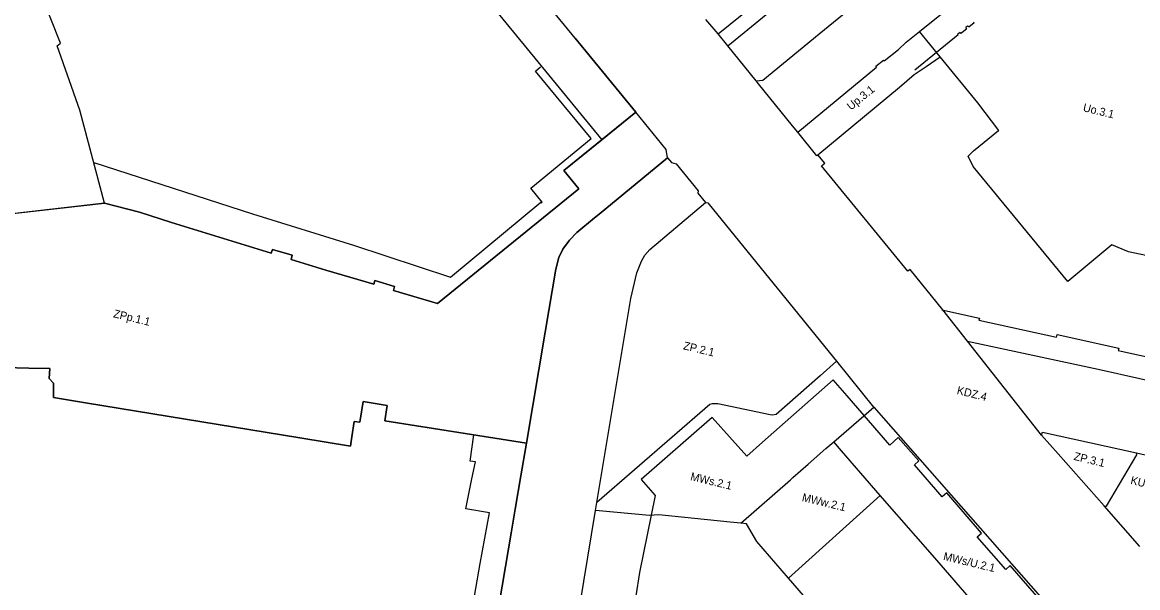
# Model space of a CAD drawing. Extents: x 7429686 to 7432896, y 5547954 to 5550600.
# Drawn here: x 7430296 to 7430853, y 5549179 to 5549462 of the extents above; entities that cross this region are included whole.
import ezdxf

# ---------------------------------------------------------------- set-up
doc = ezdxf.new("R2010")
doc.units = 0
for name, color, linetype in [('linie rozgraniczające', 7, 'Continuous'), ('nieprzekraczalna linia zabudowy', 7, 'Continuous'), ('obowiązująca linia zabudowy', 7, 'Continuous'), ('oznaczenia przeznaczeń', 7, 'Continuous')]:
    doc.layers.add(name, color=color, linetype=linetype)

msp = doc.modelspace()

# ---------------------------------------------------------------- linework, layer by layer
at = {"layer": 'linie rozgraniczające'}
for p, q in [((7430572.38, 5549453.75), (7430602.76, 5549416.71)), ((7430602.76, 5549416.71), (7430566.84, 5549387.58)), ((7430617.97, 5549398.17), (7430602.76, 5549416.71)), ((7430618.59, 5549393.98), (7430617.97, 5549398.17)), ((7430584.47, 5549365.84), (7430618.59, 5549393.98)), ((7430566.84, 5549387.58), (7430574.26, 5549378.42)), ((7430574.26, 5549378.42), (7430503.7, 5549321.19)), ((7430337.34, 5549371.27), (7430272.16, 5549363.93)), ((7430354.77, 5549366.88), (7430337.34, 5549371.27)), ((7430370.74, 5549361.7), (7430354.77, 5549366.88)), ((7430420.6, 5549346.33), (7430370.74, 5549361.7)), ((7430421.24, 5549348.13), (7430420.6, 5549346.33)), ((7430431.09, 5549345.3), (7430421.24, 5549348.13)), ((7430564.26, 5549344.2), (7430566.35, 5549348.4)), ((7430430.65, 5549343.27), (7430431.09, 5549345.3)), ((7430447.94, 5549337.81), (7430430.65, 5549343.27)), ((7430562.78, 5549338.29), (7430564.26, 5549344.2)), ((7430471.79, 5549330.8), (7430447.94, 5549337.81)), ((7430557.54, 5549307), (7430562.78, 5549338.29)), ((7430472.33, 5549332.69), (7430471.79, 5549330.8)), ((7430482.21, 5549329.77), (7430472.33, 5549332.69)), ((7430481.77, 5549327.66), (7430482.21, 5549329.77)), ((7430503.7, 5549321.19), (7430481.77, 5549327.66)), ((7430548.12, 5549251.59), (7430557.54, 5549307)), ((7430299.57, 5549289), (7430310.07, 5549288.78)), ((7430310.07, 5549288.78), (7430299.57, 5549289)), ((7430310.07, 5549288.78), (7430309.7, 5549283.85)), ((7430309.7, 5549283.85), (7430310.07, 5549288.78)), ((7430309.7, 5549283.85), (7430311.83, 5549281.48)), ((7430311.83, 5549281.48), (7430309.7, 5549283.85)), ((7430460.96, 5549254.64), (7430462.06, 5549262.36)), ((7430462.06, 5549262.36), (7430460.96, 5549254.64)), ((7430477.31, 5549262.67), (7430548.12, 5549251.59)), ((7430548.12, 5549251.59), (7430477.31, 5549262.67))]:
    msp.add_line(p, q, dxfattribs=at)
for points in [[(7430694.34, 5549455.8), (7430768.57, 5549516.43)], [(7430500.44, 5549507), (7430585.7, 5549402.87)], [(7430648.77, 5549449.84), (7430699.66, 5549491.66)], [(7430572.38, 5549453.75), (7430546.44, 5549485.44)], [(7430315.31, 5549451.27), (7430305.6, 5549475.67)], [(7430744.44, 5549457), (7430755.42, 5549465.8)], [(7430643.85, 5549455.8), (7430637.8, 5549463.05)], [(7430602.76, 5549416.71), (7430572.38, 5549453.75)], [(7430648.77, 5549449.84), (7430643.85, 5549455.8)], [(7430666.17, 5549432.65), (7430694.34, 5549455.8)], [(7430737.8, 5549451.68), (7430744.44, 5549457)], [(7430754.83, 5549444.29), (7430744.44, 5549457)], [(7430313.63, 5549449.85), (7430315.31, 5549451.27)], [(7430324.98, 5549417.82), (7430313.63, 5549449.85)], [(7430662.88, 5549432.41), (7430648.77, 5549449.84)], [(7430726.87, 5549442.35), (7430734.04, 5549448)], [(7430734.04, 5549448), (7430737.8, 5549451.68)], [(7430722.71, 5549439.66), (7430726.46, 5549442.73)], [(7430726.46, 5549442.73), (7430726.87, 5549442.35)], [(7430747.87, 5549439.58), (7430754.83, 5549444.29)], [(7430773.6, 5549421.33), (7430754.83, 5549444.29)], [(7430683.69, 5549406.71), (7430722.96, 5549439.25)], [(7430722.96, 5549439.25), (7430722.71, 5549439.66)], [(7430741.81, 5549435.48), (7430747.87, 5549439.58)], [(7430662.88, 5549432.41), (7430666.17, 5549432.65)], [(7430664.07, 5549430.93), (7430662.88, 5549432.41)], [(7430681.11, 5549409.99), (7430664.07, 5549430.93)], [(7430734.41, 5549429.24), (7430741.81, 5549435.48)], [(7430693.66, 5549395.47), (7430734.41, 5549429.24)], [(7430784.03, 5549407.63), (7430773.6, 5549421.33)], [(7430337.34, 5549371.27), (7430324.98, 5549417.82)], [(7430585.7, 5549402.87), (7430602.76, 5549416.71)], [(7430683.69, 5549406.71), (7430681.11, 5549409.99)], [(7430337.34, 5549371.27), (7430354.77, 5549366.88), (7430370.74, 5549361.7), (7430420.6, 5549346.33), (7430421.24, 5549348.13), (7430431.09, 5549345.3), (7430430.65, 5549343.27), (7430447.94, 5549337.81), (7430471.79, 5549330.8), (7430472.33, 5549332.69), (7430482.21, 5549329.77), (7430481.77, 5549327.66), (7430503.7, 5549321.19), (7430574.26, 5549378.42), (7430566.84, 5549387.58), (7430585.7, 5549402.87)], [(7430693.14, 5549395.03), (7430683.69, 5549406.71)], [(7430771.5, 5549397.49), (7430783.91, 5549407.54)], [(7430783.91, 5549407.54), (7430784.03, 5549407.63)], [(7430768.87, 5549394.83), (7430771.5, 5549397.49)], [(7430618.59, 5549393.98), (7430584.47, 5549365.84), (7430582.03, 5549363.94), (7430573.22, 5549356.61), (7430569.64, 5549352.91), (7430566.35, 5549348.4), (7430564.26, 5549344.2), (7430562.78, 5549338.29), (7430557.54, 5549307), (7430548.12, 5549251.59), (7430545.34, 5549235.21), (7430542.51, 5549218.56), (7430540.65, 5549207.55), (7430533.01, 5549162.52), (7430527.32, 5549127.87), (7430525.7, 5549118.01), (7430522.95, 5549101.23), (7430520.88, 5549089.31), (7430518.75, 5549077.07)], [(7430618.59, 5549393.98), (7430620.66, 5549391.55)], [(7430620.66, 5549391.55), (7430622.95, 5549390.88)], [(7430693.66, 5549395.47), (7430693.14, 5549395.03)], [(7430697.19, 5549391.24), (7430693.66, 5549395.47)], [(7430695.58, 5549389.89), (7430697.19, 5549391.24)], [(7430771.22, 5549389.57), (7430768.87, 5549394.83)], [(7430622.95, 5549390.88), (7430633.84, 5549377.42)], [(7430738.69, 5549337.39), (7430695.58, 5549389.89)], [(7430818.63, 5549332.25), (7430771.22, 5549389.57)], [(7430633.84, 5549377.42), (7430633.81, 5549376.39)], [(7430633.81, 5549376.39), (7430637.56, 5549371.57)], [(7430243.28, 5549369.29), (7430272.16, 5549363.93), (7430337.34, 5549371.27)], [(7430609.71, 5549348.2), (7430637.56, 5549371.57)], [(7430637.56, 5549371.57), (7430638.8, 5549371.41)], [(7430638.8, 5549371.41), (7430643.75, 5549365.32)], [(7430566.35, 5549348.4), (7430569.64, 5549352.91), (7430573.22, 5549356.61), (7430582.03, 5549363.94), (7430584.47, 5549365.84)], [(7430643.75, 5549365.32), (7430703.02, 5549292.37)], [(7430607.29, 5549345.32), (7430609.71, 5549348.2)], [(7430840.53, 5549350.59), (7430818.63, 5549332.25)], [(7430848.84, 5549346.95), (7430840.53, 5549350.59)], [(7430882.06, 5549340.05), (7430848.84, 5549346.95)], [(7430603.19, 5549336.62), (7430605.58, 5549342.31)], [(7430605.58, 5549342.31), (7430607.29, 5549345.32)], [(7430600.3, 5549323.68), (7430603.19, 5549336.62)], [(7430739.78, 5549338.18), (7430738.69, 5549337.39)], [(7430756.09, 5549318.13), (7430739.78, 5549338.18)], [(7430585.73, 5549236.85), (7430600.3, 5549323.68)], [(7430768.46, 5549302.43), (7430756.09, 5549318.13)], [(7430805.47, 5549255.48), (7430768.46, 5549302.43)], [(7430768.46, 5549302.43), (7430833.66, 5549288.37)], [(7430703.02, 5549292.37), (7430694.84, 5549285.16)], [(7430703.02, 5549292.37), (7430721.55, 5549269.55)], [(7430267.43, 5549289.84), (7430287.43, 5549289.21), (7430299.57, 5549289)], [(7430299.57, 5549289), (7430287.43, 5549289.21), (7430267.43, 5549289.84)], [(7430694.84, 5549285.16), (7430672.79, 5549265.74)], [(7430833.66, 5549288.37), (7430896.14, 5549274.49)], [(7430311.83, 5549281.48), (7430311.88, 5549274.24), (7430327.8, 5549271.63), (7430434.82, 5549254.16)], [(7430434.82, 5549254.16), (7430327.8, 5549271.63), (7430311.88, 5549274.24), (7430311.83, 5549281.48)], [(7430462.06, 5549262.36), (7430464.85, 5549262), (7430466.57, 5549272.33), (7430478.51, 5549270.29), (7430477.31, 5549262.67)], [(7430477.31, 5549262.67), (7430478.51, 5549270.29), (7430466.57, 5549272.33), (7430464.85, 5549262), (7430462.06, 5549262.36)], [(7430639.76, 5549270.8), (7430583.23, 5549221.89)], [(7430640.82, 5549271.09), (7430639.76, 5549270.8)], [(7430643.71, 5549271.17), (7430640.82, 5549271.09)], [(7430669.95, 5549265.61), (7430643.71, 5549271.17)], [(7430701.6, 5549252.19), (7430721.61, 5549269.49)], [(7430721.55, 5549269.55), (7430721.61, 5549269.49)], [(7430721.61, 5549269.49), (7430744.67, 5549243.3)], [(7430671.02, 5549265.52), (7430669.95, 5549265.61)], [(7430672.79, 5549265.74), (7430671.02, 5549265.52)], [(7430434.82, 5549254.16), (7430460.21, 5549250.09), (7430460.96, 5549254.64)], [(7430460.96, 5549254.64), (7430460.21, 5549250.09), (7430434.82, 5549254.16)], [(7430697.66, 5549248.78), (7430701.6, 5549252.19)], [(7430705.58, 5549247.62), (7430701.6, 5549252.19)], [(7430805.47, 5549255.48), (7430805.92, 5549257.02)], [(7430813.77, 5549246.1), (7430805.47, 5549255.48)], [(7430805.92, 5549257.02), (7430852.85, 5549246.65)], [(7430542.51, 5549218.56), (7430545.34, 5549235.21), (7430548.12, 5549251.59)], [(7430688.81, 5549241.03), (7430697.66, 5549248.78)], [(7430724.9, 5549225.36), (7430705.58, 5549247.62)], [(7430836.68, 5549220.22), (7430813.77, 5549246.1)], [(7430852.85, 5549246.65), (7430880.45, 5549240.36)], [(7430853.06, 5549245.68), (7430852.85, 5549246.65)], [(7430681.16, 5549234.33), (7430688.81, 5549241.03)], [(7430744.67, 5549243.3), (7430820.61, 5549157.06)], [(7430837.85, 5549219.98), (7430853.06, 5549245.68)], [(7430583.23, 5549221.89), (7430585.73, 5549236.85)], [(7430655.21, 5549211.6), (7430679.95, 5549233.27)], [(7430679.95, 5549233.27), (7430681.16, 5549234.33)], [(7430678.99, 5549184.08), (7430724.9, 5549225.36)], [(7430742.58, 5549205.06), (7430724.9, 5549225.36)], [(7430527.32, 5549127.87), (7430533.01, 5549162.52), (7430540.65, 5549207.55), (7430542.51, 5549218.56)], [(7430582.56, 5549217.92), (7430583.23, 5549221.89)], [(7430846.27, 5549209.39), (7430836.68, 5549220.22)], [(7430836.68, 5549220.22), (7430837.85, 5549219.98)], [(7430569.17, 5549135.83), (7430582.56, 5549217.92)], [(7430609.52, 5549215.41), (7430582.56, 5549217.92)], [(7430614.29, 5549215.75), (7430609.52, 5549215.41)], [(7430649.97, 5549212.13), (7430614.29, 5549215.75)], [(7430655.21, 5549211.6), (7430649.97, 5549212.13)], [(7430658.09, 5549211.3), (7430655.21, 5549211.6)], [(7430663.18, 5549202.47), (7430658.09, 5549211.3)], [(7430854.62, 5549199.88), (7430846.27, 5549209.39)], [(7430678.99, 5549184.08), (7430663.18, 5549202.47)], [(7430750.91, 5549195.58), (7430742.58, 5549205.06)], [(7430773.65, 5549169.45), (7430750.91, 5549195.58)], [(7430734.87, 5549119.69), (7430678.99, 5549184.08)]]:
    msp.add_lwpolyline(points, dxfattribs=at)
at = {"layer": 'nieprzekraczalna linia zabudowy'}
msp.add_lwpolyline([(7430331.95, 5549391.55), (7430411.23, 5549365.95), (7430461.67, 5549350.35), (7430510.16, 5549334.34)], dxfattribs=at)
at = {"layer": 'obowiązująca linia zabudowy'}
for points in [[(7430643.85, 5549455.8), (7430667.83, 5549475.39), (7430675.07, 5549481.21), (7430684.17, 5549488.72)], [(7430771.53, 5549461.6), (7430771.73, 5549461.33), (7430769.15, 5549459.19), (7430768.88, 5549459.51), (7430768.39, 5549459.6), (7430767.69, 5549459.06), (7430767.62, 5549458.66), (7430767.9, 5549458.25), (7430765.21, 5549456.03), (7430764.75, 5549456.59), (7430763.8, 5549455.85)], [(7430763.8, 5549455.85), (7430763.51, 5549455.63), (7430763.75, 5549455.28), (7430742.21, 5549437.78)], [(7430510.16, 5549334.34), (7430555.33, 5549371.75), (7430555.5, 5549371.54), (7430555.93, 5549371.89), (7430550.29, 5549378.76), (7430580.37, 5549403.55), (7430552.69, 5549437.26), (7430555.13, 5549439.42)], [(7430755.67, 5549318.05), (7430774.38, 5549313.89), (7430774.18, 5549312.91), (7430813, 5549304.47), (7430813.33, 5549305.68), (7430844.07, 5549298.91), (7430843.76, 5549297.83), (7430882.61, 5549289.2), (7430882.88, 5549290.42), (7430924.94, 5549281.21), (7430923.68, 5549275.55), (7431011.35, 5549256.65)], [(7430807.46, 5549170.15), (7430789.79, 5549190.42), (7430787.53, 5549188.42), (7430773.32, 5549204.67), (7430775.38, 5549206.6), (7430758.17, 5549226.67), (7430755.83, 5549224.71), (7430741.96, 5549240.7), (7430744.22, 5549242.69), (7430733.76, 5549254.26), (7430729.61, 5549250.52), (7430708.27, 5549275.1), (7430701.36, 5549283.05), (7430666.02, 5549251.93), (7430658.16, 5549245), (7430640.87, 5549264.28), (7430605.46, 5549233.36), (7430612.5, 5549225.35), (7430604.66, 5549186.89), (7430602.72, 5549175.29)], [(7430508.14, 5549091.41), (7430509.71, 5549101.11), (7430511.71, 5549112.65), (7430517.38, 5549146.41), (7430519.17, 5549157.79), (7430524.99, 5549191.5), (7430529.58, 5549216.68), (7430517.79, 5549218.75), (7430520.89, 5549233.72), (7430522.65, 5549242.2), (7430519.94, 5549242.49), (7430521.85, 5549255.7)]]:
    msp.add_lwpolyline(points, dxfattribs=at)

# ---------------------------------------------------------------- texts
at = {"layer": 'oznaczenia przeznaczeń'}
for s, rotation, p in [('Up.3.1', 38.9279, (7430710.21, 5549417.5)), ('Uo.3.1', 346.4891, (7430825.88, 5549417.29)), ('ZPp.1.1', 346.4891, (7430341.44, 5549314.42)), ('ZP.2.1', 346.4891, (7430626.18, 5549298.43)), ('KDZ.4', 346.4891, (7430762.86, 5549276.11)), ('ZP.3.1', 346.4891, (7430821.27, 5549243.22)), ('MWs.2.1', 346.4891, (7430629.75, 5549233.11)), ('KU.3.1', 346.4891, (7430849.62, 5549231.21)), ('MWw.2.1', 346.4891, (7430685.49, 5549222.68)), ('MWs/U.2.1', 346.4891, (7430756.08, 5549193.29))]:
    msp.add_text(s, height=4, rotation=rotation, dxfattribs=at).set_placement(p)

doc.saveas('drawing.dxf')
